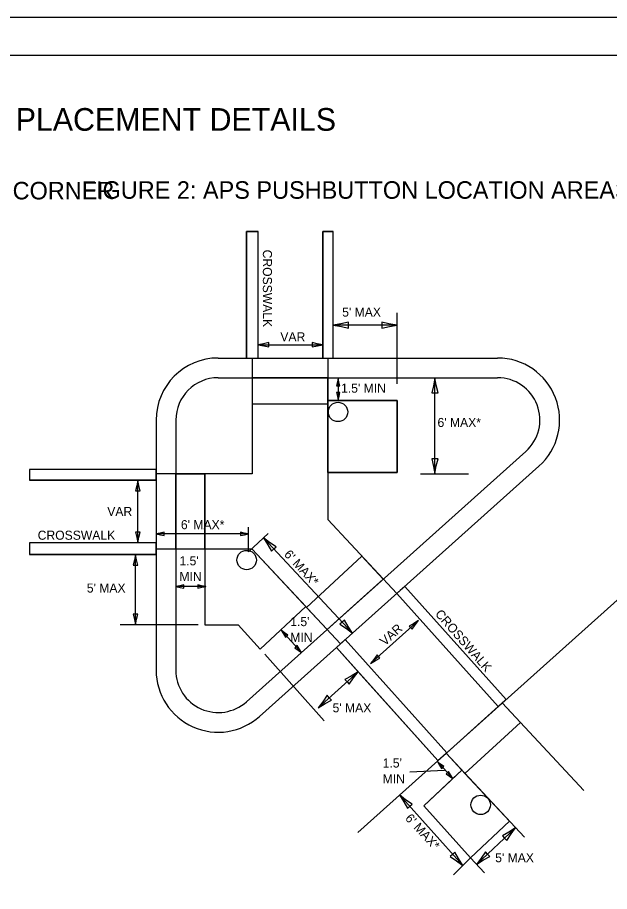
# Model space of a CAD drawing. Extents: x 1896459 to 1901611, y 1616229 to 1617416.
# Drawn here: x 1897089 to 1897481, y 1616838 to 1617416 of the extents above; entities that cross this region are included whole.
import ezdxf

# ---------------------------------------------------------------- set-up
doc = ezdxf.new("R2010")
doc.units = 0
for name, color, linetype in [('Level 24', 7, 'Continuous'), ('Level 32', 7, 'Continuous'), ('Level 8', 7, 'Continuous'), ('Sheets_General Details', 7, 'Continuous')]:
    doc.layers.add(name, color=color, linetype=linetype)

msp = doc.modelspace()

# ---------------------------------------------------------------- linework, layer by layer
at = {"layer": 'Level 24'}
for p, q in [((1897240.83, 1617274.92), (1897248.6, 1617274.92)), ((1897240.83, 1617274.92), (1897240.83, 1617191.24)), ((1897248.6, 1617274.92), (1897240.83, 1617274.92)), ((1897248.6, 1617191.24), (1897248.6, 1617274.92)), ((1897291.23, 1617274.92), (1897298.26, 1617274.92)), ((1897291.23, 1617274.92), (1897291.23, 1617191.24)), ((1897298.26, 1617274.92), (1897291.23, 1617274.92)), ((1897097.44, 1617117.46), (1897097.44, 1617110.43)), ((1897181.12, 1617117.46), (1897097.44, 1617117.46)), ((1897097.44, 1617117.46), (1897097.44, 1617110.43)), ((1897097.44, 1617110.43), (1897181.12, 1617110.43)), ((1897097.44, 1617068.93), (1897097.44, 1617061.16)), ((1897181.12, 1617068.93), (1897097.44, 1617068.93)), ((1897097.44, 1617068.93), (1897097.44, 1617061.16)), ((1897412.45, 1616965.32), (1897345.44, 1617040.12)), ((1897340.21, 1617035.43), (1897407.22, 1616960.63)), ((1897373.21, 1616930.16), (1897306.2, 1617004.97))]:
    msp.add_line(p, q, dxfattribs=at)
for points in [[(1897298.26, 1617191.24), (1897298.26, 1617212.96), (1897298.26, 1617274.92)], [(1897240.83, 1617191.24), (1897244.67, 1617191.24), (1897248.6, 1617191.24)], [(1897291.23, 1617191.24), (1897294.56, 1617191.24), (1897298.26, 1617191.24)], [(1897181.12, 1617110.43), (1897181.12, 1617114.58), (1897181.12, 1617117.46)], [(1897181.12, 1617061.16), (1897181.12, 1617064.69), (1897181.12, 1617068.93)], [(1897097.44, 1617061.16), (1897167.48, 1617061.16), (1897181.12, 1617061.16)], [(1897345.44, 1617040.12), (1897342.46, 1617037.45), (1897340.21, 1617035.43)], [(1897306.2, 1617004.97), (1897303.05, 1617002.14), (1897300.41, 1616999.78)], [(1897300.41, 1616999.78), (1897314.78, 1616983.74), (1897367.42, 1616924.98)], [(1897407.22, 1616960.63), (1897412.2, 1616965.09), (1897412.45, 1616965.32)], [(1897367.42, 1616924.98), (1897372.78, 1616929.78), (1897373.21, 1616930.16)]]:
    msp.add_lwpolyline(points, dxfattribs=at)
at = {"layer": 'Level 32'}
for p, q in [((1897240.83, 1617191.24), (1897240.83, 1617274.92)), ((1897248.6, 1617191.24), (1897248.6, 1617274.92)), ((1897291.23, 1617191.24), (1897291.23, 1617274.92)), ((1897298.26, 1617191.24), (1897298.26, 1617274.92)), ((1897181.12, 1617117.46), (1897097.44, 1617117.46)), ((1897181.12, 1617110.43), (1897097.44, 1617110.43)), ((1897181.12, 1617068.93), (1897097.44, 1617068.93)), ((1897181.12, 1617061.16), (1897097.44, 1617061.16)), ((1897412.45, 1616965.32), (1897345.44, 1617040.12)), ((1897407.22, 1616960.63), (1897340.21, 1617035.43)), ((1897373.21, 1616930.16), (1897306.2, 1617004.97)), ((1897367.42, 1616924.98), (1897300.41, 1616999.78))]:
    msp.add_line(p, q, dxfattribs=at)
at = {"layer": 'Level 8'}
for p, q in [((1897340.4, 1617174.06), (1897340.4, 1617221.04)), ((1897340.4, 1617212.96), (1897298.26, 1617212.96)), ((1897248.6, 1617199.99), (1897291.23, 1617199.99)), ((1897301.46, 1617178.21), (1897301.56, 1617163.16)), ((1897365.38, 1617114.58), (1897365.38, 1617178.21)), ((1897355.82, 1617114.58), (1897387.73, 1617114.58)), ((1897169.01, 1617069.07), (1897169.01, 1617110.43)), ((1897242.26, 1617063.1), (1897242.26, 1617079.43)), ((1897242.26, 1617074.85), (1897181.12, 1617074.85)), ((1897242.26, 1617063.1), (1897255.28, 1617075.25)), ((1897252.06, 1617072.24), (1897310.91, 1617009.19)), ((1897167.48, 1617014.81), (1897167.48, 1617061.16)), ((1897214.07, 1617040.02), (1897194.15, 1617040.02)), ((1897208.82, 1617014.81), (1897157.32, 1617014.81)), ((1897322.91, 1616989.09), (1897354.66, 1617017.54)), ((1897263.86, 1617011.21), (1897277.12, 1616996.41)), ((1897252.89, 1616995.34), (1897292.28, 1616951.35)), ((1897288.16, 1616959.89), (1897314.78, 1616983.74)), ((1897367.03, 1616924.38), (1897377.22, 1616913)), ((1897371.82, 1616918.42), (1897348.75, 1616917.37)), ((1897383.81, 1616855.51), (1897341.99, 1616902.2)), ((1897392.95, 1616856.33), (1897418.81, 1616880.47))]:
    msp.add_line(p, q, dxfattribs=at)
for points in [[(1897308.26, 1617210.87), (1897308.26, 1617212.96), (1897308.26, 1617215.05), (1897303.26, 1617213.83), (1897298.26, 1617212.96), (1897303.59, 1617211.99)], [(1897330.4, 1617215.05), (1897330.4, 1617212.96), (1897330.4, 1617210.87), (1897335.4, 1617212.1), (1897340.4, 1617212.96), (1897335.07, 1617213.93)], [(1897255.6, 1617198.53), (1897255.6, 1617199.99), (1897255.6, 1617201.45), (1897252.1, 1617200.6), (1897248.6, 1617199.99), (1897252.33, 1617199.31)], [(1897284.23, 1617201.45), (1897284.23, 1617199.99), (1897284.23, 1617198.53), (1897287.73, 1617199.38), (1897291.23, 1617199.99), (1897287.5, 1617200.67)], [(1897300.38, 1617172.87), (1897301.5, 1617172.88), (1897302.61, 1617172.88), (1897301.94, 1617175.55), (1897301.46, 1617178.21), (1897300.96, 1617175.36)], [(1897363.29, 1617168.21), (1897365.38, 1617168.21), (1897367.47, 1617168.21), (1897366.25, 1617173.21), (1897365.38, 1617178.21), (1897364.41, 1617172.88)], [(1897302.64, 1617168.5), (1897301.53, 1617168.5), (1897300.41, 1617168.49), (1897301.08, 1617165.83), (1897301.56, 1617163.16), (1897302.06, 1617166.01)], [(1897367.47, 1617124.58), (1897365.38, 1617124.58), (1897363.29, 1617124.58), (1897364.51, 1617119.58), (1897365.38, 1617114.58), (1897366.35, 1617119.91)], [(1897167.54, 1617103.43), (1897169.01, 1617103.42), (1897170.47, 1617103.42), (1897169.61, 1617106.92), (1897169.01, 1617110.42), (1897168.33, 1617106.69)], [(1897170.47, 1617076.07), (1897169.01, 1617076.07), (1897167.54, 1617076.07), (1897168.4, 1617072.57), (1897169.01, 1617069.07), (1897169.68, 1617072.8)], [(1897186.45, 1617073.73), (1897186.45, 1617074.85), (1897186.45, 1617075.96), (1897183.79, 1617075.31), (1897181.12, 1617074.85), (1897183.96, 1617074.33)], [(1897236.93, 1617075.96), (1897236.93, 1617074.85), (1897236.93, 1617073.73), (1897239.6, 1617074.38), (1897242.26, 1617074.85), (1897239.42, 1617075.36)], [(1897257.35, 1617063.51), (1897258.88, 1617064.93), (1897260.41, 1617066.36), (1897256.1, 1617069.18), (1897252.06, 1617072.24), (1897254.99, 1617067.68)], [(1897166.02, 1617054.16), (1897167.48, 1617054.16), (1897168.95, 1617054.16), (1897168.09, 1617057.66), (1897167.48, 1617061.16), (1897166.81, 1617057.43)], [(1897199.48, 1617038.91), (1897199.48, 1617040.02), (1897199.48, 1617041.14), (1897196.81, 1617040.48), (1897194.15, 1617040.02), (1897196.99, 1617039.5)], [(1897208.74, 1617041.14), (1897208.73, 1617040.02), (1897208.73, 1617038.91), (1897211.4, 1617039.56), (1897214.07, 1617040.02), (1897211.22, 1617040.54)], [(1897168.95, 1617021.8), (1897167.48, 1617021.81), (1897166.02, 1617021.81), (1897166.88, 1617018.31), (1897167.48, 1617014.81), (1897168.16, 1617018.54)], [(1897305.62, 1617017.93), (1897304.09, 1617016.5), (1897302.56, 1617015.08), (1897306.87, 1617012.25), (1897310.91, 1617009.19), (1897307.98, 1617013.75)], [(1897348.48, 1617013.96), (1897349.45, 1617012.87), (1897350.43, 1617011.78), (1897352.46, 1617014.75), (1897354.66, 1617017.54), (1897351.43, 1617015.55)], [(1897266.59, 1617006.49), (1897267.42, 1617007.23), (1897268.25, 1617007.98), (1897265.98, 1617009.53), (1897263.86, 1617011.21), (1897265.37, 1617008.74)], [(1897274.39, 1617001.12), (1897273.56, 1617000.38), (1897272.73, 1616999.64), (1897275, 1616998.08), (1897277.12, 1616996.41), (1897275.61, 1616998.87)], [(1897329.1, 1616992.67), (1897328.12, 1616993.76), (1897327.15, 1616994.85), (1897325.11, 1616991.88), (1897322.91, 1616989.09), (1897326.14, 1616991.08)], [(1897305.94, 1616978.62), (1897307.33, 1616977.06), (1897308.73, 1616975.5), (1897311.63, 1616979.76), (1897314.78, 1616983.74), (1897310.16, 1616980.9)], [(1897297, 1616965), (1897295.61, 1616966.57), (1897294.22, 1616968.12), (1897291.31, 1616963.87), (1897288.16, 1616959.89), (1897292.78, 1616962.73)], [(1897369.75, 1616919.66), (1897370.59, 1616920.4), (1897371.42, 1616921.15), (1897369.15, 1616922.7), (1897367.03, 1616924.38), (1897368.54, 1616921.91)], [(1897374.49, 1616917.72), (1897373.66, 1616916.98), (1897372.83, 1616916.23), (1897375.09, 1616914.68), (1897377.22, 1616913), (1897375.7, 1616915.47)], [(1897347.21, 1616893.41), (1897348.75, 1616894.82), (1897350.29, 1616896.24), (1897346.01, 1616899.1), (1897341.99, 1616902.2), (1897344.88, 1616897.61)], [(1897410.07, 1616875.17), (1897411.5, 1616873.64), (1897412.93, 1616872.11), (1897415.75, 1616876.42), (1897418.81, 1616880.47), (1897414.25, 1616877.54)], [(1897378.6, 1616864.29), (1897377.05, 1616862.88), (1897375.51, 1616861.47), (1897379.8, 1616858.61), (1897383.81, 1616855.51), (1897380.92, 1616860.1)], [(1897401.69, 1616861.62), (1897400.26, 1616863.15), (1897398.83, 1616864.68), (1897396.01, 1616860.37), (1897392.95, 1616856.33), (1897397.51, 1616859.26)]]:
    msp.add_lwpolyline(points, close=True, dxfattribs=at)
at = {"layer": 'Sheets_General Details'}
for p, q in [((1898159.07, 1617416.47), (1896459.07, 1617416.47)), ((1897222.15, 1617191.24), (1897406.85, 1617191.24)), ((1897244.67, 1617191.24), (1897244.67, 1617114.58)), ((1897294.56, 1617191.24), (1897294.56, 1617084.34)), ((1897222.15, 1617178.21), (1897406.85, 1617178.21)), ((1897294.56, 1617178.21), (1897244.67, 1617178.21)), ((1897244.67, 1617178.21), (1897244.67, 1617160.85)), ((1897294.56, 1617178.21), (1897244.67, 1617178.21)), ((1897244.67, 1617178.21), (1897244.67, 1617160.85)), ((1897294.56, 1617163.03), (1897294.56, 1617178.21)), ((1897294.56, 1617163.03), (1897294.56, 1617178.21)), ((1897244.67, 1617160.85), (1897294.56, 1617160.85)), ((1897244.67, 1617160.85), (1897294.56, 1617160.85)), ((1897244.67, 1617160.85), (1897294.56, 1617160.85)), ((1897294.56, 1617163.03), (1897294.56, 1617160.85)), ((1897294.56, 1617160.85), (1897294.56, 1617163.03)), ((1897294.56, 1617160.85), (1897294.56, 1617163.03)), ((1897294.56, 1617160.85), (1897294.56, 1617115.61)), ((1897181.12, 1617150.21), (1897181.12, 1616984.75)), ((1897194.15, 1617150.21), (1897194.15, 1616984.75)), ((1897425.54, 1617129.36), (1897240.83, 1616963.9)), ((1897434.23, 1617119.65), (1897249.52, 1616954.2)), ((1897244.67, 1617114.58), (1897181.12, 1617114.58)), ((1897213.26, 1617064.69), (1897213.26, 1617114.58)), ((1897294.56, 1617084.34), (1897340.21, 1617035.43)), ((1897244.67, 1617064.69), (1897181.12, 1617064.69)), ((1897213.26, 1617064.69), (1897213.26, 1617014.81)), ((1897242.26, 1617064.69), (1897213.26, 1617064.69)), ((1897213.26, 1617064.69), (1897213.26, 1617040.17)), ((1897243.96, 1617064.69), (1897242.26, 1617063.1)), ((1897242.26, 1617063.1), (1897242.26, 1617064.69)), ((1897244.67, 1617064.69), (1897243.96, 1617064.69)), ((1897244.67, 1617064.69), (1897303.05, 1617002.14)), ((1897280, 1617026.84), (1897244.67, 1617064.69)), ((1897280.57, 1617026.22), (1897317.04, 1617060.26)), ((1897499.12, 1617042.95), (1897314.41, 1616877.49)), ((1897213.26, 1617039.88), (1897213.26, 1617014.81)), ((1897249.86, 1616998.71), (1897280.07, 1617026.9)), ((1897249.86, 1616998.71), (1897280, 1617026.84)), ((1897213.26, 1617014.81), (1897235.44, 1617014.81)), ((1897213.26, 1617014.81), (1897235.44, 1617014.81)), ((1897249.86, 1616998.71), (1897235.44, 1617014.81)), ((1897235.44, 1617014.81), (1897249.86, 1616998.71)), ((1897248.24, 1617000.63), (1897248.24, 1617000.63)), ((1897409.94, 1616963.07), (1897407.22, 1616960.63)), ((1897409.94, 1616963.07), (1897463.93, 1616905.24)), ((1897421.97, 1616950.19), (1897409.94, 1616963.07)), ((1897407.22, 1616960.63), (1897373.21, 1616930.16)), ((1897385.29, 1616916.38), (1897421.97, 1616950.19)), ((1897385.29, 1616916.38), (1897421.97, 1616950.19)), ((1897373.21, 1616930.16), (1897372.78, 1616929.78)), ((1897372.78, 1616929.78), (1897424.57, 1616874.3)), ((1897372.78, 1616929.78), (1897383.22, 1616918.6)), ((1897358, 1616895.07), (1897383.22, 1616918.6)), ((1897383.22, 1616918.6), (1897385.29, 1616916.38)), ((1897388.88, 1616860.6), (1897358, 1616895.07)), ((1897358, 1616895.07), (1897388.88, 1616860.6)), ((1897388.88, 1616860.6), (1897414.78, 1616884.78)), ((1897388.88, 1616860.6), (1897414.78, 1616884.78)), ((1897377.69, 1616849.36), (1897388.88, 1616860.6)), ((1897388.88, 1616860.6), (1897398.28, 1616850.73))]:
    msp.add_line(p, q, dxfattribs=at)
for points in [[(1896459.07, 1616316.47), (1898159.07, 1616316.47), (1898159.07, 1617416.47), (1896459.07, 1617416.47)], [(1896559.07, 1617391.47), (1898134.07, 1617391.47), (1898134.07, 1616341.47), (1896559.07, 1616341.47)], [(1896559.07, 1617391.46), (1898134.07, 1617391.46), (1898134.07, 1616391.47), (1896559.07, 1616391.47)], [(1897340.56, 1617115.61), (1897294.56, 1617115.61), (1897294.56, 1617163.03), (1897340.56, 1617163.03)], [(1897194.15, 1617114.58), (1897213.26, 1617114.58), (1897213.26, 1617064.69), (1897194.15, 1617064.69)], [(1897280.57, 1617026.22), (1897317.04, 1617060.26), (1897331.32, 1617044.96), (1897294.16, 1617011.67)]]:
    msp.add_lwpolyline(points, close=True, dxfattribs=at)
for points in [[(1897294.56, 1617115.61), (1897340.56, 1617115.61), (1897340.56, 1617163.03), (1897294.56, 1617163.03)], [(1897213.26, 1617040.17), (1897214.07, 1617040.02), (1897213.26, 1617039.88)], [(1897383.22, 1616918.6), (1897377.22, 1616913), (1897358, 1616895.07)], [(1897414.78, 1616884.78), (1897385.29, 1616916.38), (1897383.22, 1616918.6)]]:
    msp.add_lwpolyline(points, dxfattribs=at)
for centre in [(1897301.38, 1617155.54), (1897240.98, 1617057.61), (1897395.69, 1616895.68)]:
    msp.add_circle(centre, 6.41, dxfattribs=at)
for centre, radius, start, end in [((1897222.15, 1617150.21), 41.03, 90, 180), ((1897406.85, 1617150.21), 41.03, 311.8532, 90), ((1897222.15, 1617150.21), 28, 90, 180), ((1897406.85, 1617150.21), 28, 311.8532, 90), ((1897222.15, 1616984.75), 41.03, 180, 311.8532), ((1897222.15, 1616984.75), 28, 180, 311.8532)]:
    msp.add_arc(centre, radius, start, end, dxfattribs=at)

# ---------------------------------------------------------------- texts
at = {"layer": 'Level 24'}
msp.add_text('APS PUSHBUTTON PLACEMENT DETAILS', height=15, dxfattribs=at).set_placement((1896898.82, 1617341.55))
at = {"layer": 'Level 8'}
for s, height, p in [('FIGURE 1: APS PUSHBUTTON LOCATION AREAS - INTERSECTION CORNER', 11.6, (1896589.8, 1617296.13)), ('FIGURE 2: APS PUSHBUTTON LOCATION AREAS - CORNER ISLAND', 11.6, (1897131.93, 1617296.56)), ("5' MAX", 6, (1897304.12, 1617218.6)), ('VAR', 6, (1897263.23, 1617202.27)), ("1.5' MIN", 6, (1897303.38, 1617168.29)), ("6' MAX*", 6, (1897367.14, 1617145.6)), ('VAR', 6, (1897148.81, 1617086.71)), ("6' MAX*", 6, (1897197.52, 1617078)), ('CROSSWALK', 6, (1897102.81, 1617071.03)), ("1.5'", 6, (1897196.54, 1617054.09)), ('MIN', 6, (1897196.54, 1617043.69)), ("5' MAX", 6, (1897135.29, 1617036.08)), ("1.5'", 6, (1897269.81, 1617013.88)), ('MIN', 6, (1897269.81, 1617003.48)), ("5' MAX", 6, (1897297.77, 1616956.9)), ("1.5'", 6, (1897330.89, 1616920.34)), ('MIN', 6, (1897330.89, 1616909.94)), ("5' MAX", 6, (1897405.26, 1616857.71))]:
    msp.add_text(s, height=height, dxfattribs=at).set_placement(p)
for s, rotation, p in [('CROSSWALK', 270, (1897251.69, 1617262.92)), ("6' MAX*", 312.85493, (1897265.31, 1617060.99)), ('CROSSWALK', 311.18045, (1897365.18, 1617021.7)), ('VAR', 41.8532, (1897332.29, 1617000.55)), ("6' MAX*", 312.80104, (1897345.35, 1616886.43))]:
    msp.add_text(s, height=6, rotation=rotation, dxfattribs=at).set_placement(p)

doc.saveas('drawing.dxf')
